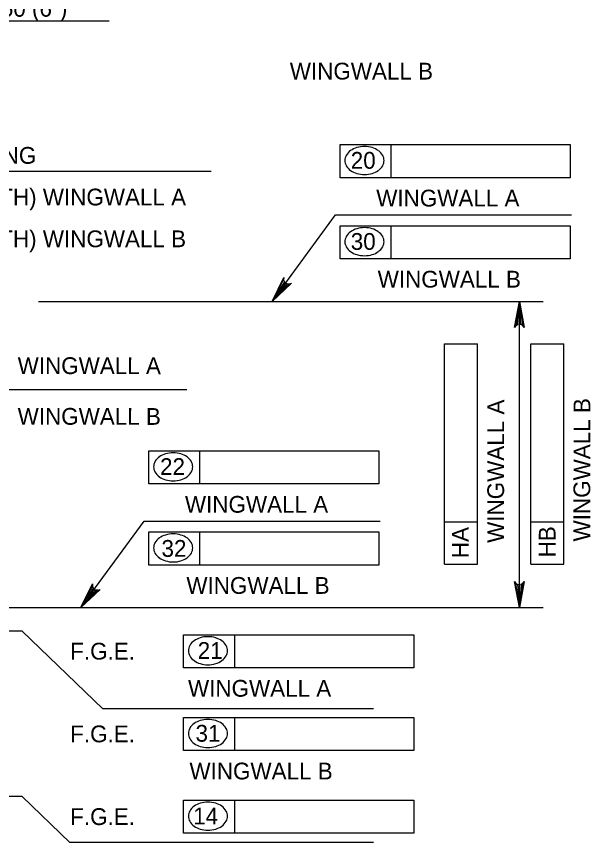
# Model space of a CAD drawing. Extents: x 635440 to 640306, y 296653 to 298484.
# Drawn here: x 638935.8 to 639038.5, y 296781 to 296928.7 of the extents above; entities that cross this region are included whole.
import ezdxf

# ---------------------------------------------------------------- set-up
doc = ezdxf.new("R2010")
doc.units = 0
doc.layers.add('5', color=7, linetype='Continuous')

msp = doc.modelspace()

# ---------------------------------------------------------------- linework, layer by layer
at = {"layer": '5'}
for p, q in [((638930.43, 296927.96), (638952.38, 296927.96)), ((638993.67, 296899.9), (638993.67, 296905.81)), ((638993.67, 296905.81), (639034.88, 296905.81)), ((639002.84, 296899.9), (639002.84, 296905.81)), ((639034.88, 296905.81), (639034.88, 296899.9)), ((638876.92, 296901.05), (638970.61, 296901.05)), ((639034.88, 296899.9), (638993.67, 296899.9)), ((638993.67, 296891.31), (639034.88, 296891.31)), ((638993.67, 296885.4), (638993.67, 296891.31)), ((639002.84, 296885.4), (639002.84, 296891.31)), ((639034.88, 296891.31), (639034.88, 296885.4)), ((639034.88, 296885.4), (638993.67, 296885.4)), ((638939.73, 296877.78), (639030.02, 296877.78)), ((639025.77, 296823.03), (639025.77, 296877.78)), ((639012.37, 296830.81), (639012.37, 296870.18)), ((639012.37, 296870.18), (639018.27, 296870.18)), ((639018.27, 296830.81), (639018.27, 296870.18)), ((639027.79, 296870.18), (639033.7, 296870.18)), ((639027.79, 296830.81), (639027.79, 296870.18)), ((639033.7, 296830.81), (639033.7, 296870.18)), ((638966.27, 296861.99), (638891.42, 296861.99)), ((638959.43, 296851.06), (639000.64, 296851.06)), ((638959.43, 296845.15), (638959.43, 296851.06)), ((638968.6, 296845.15), (638968.6, 296851.06)), ((639000.64, 296851.06), (639000.64, 296845.15)), ((639000.64, 296845.15), (638959.43, 296845.15)), ((639012.37, 296838.37), (639018.27, 296838.37)), ((639027.79, 296838.37), (639033.7, 296838.37)), ((638959.43, 296836.56), (639000.64, 296836.56)), ((638959.43, 296830.65), (638959.43, 296836.56)), ((638968.6, 296830.65), (638968.6, 296836.56)), ((639000.64, 296836.56), (639000.64, 296830.65)), ((639000.64, 296830.65), (638959.43, 296830.65)), ((639012.37, 296830.81), (639018.27, 296830.81)), ((639027.79, 296830.81), (639033.7, 296830.81)), ((638928.57, 296823.03), (639030.02, 296823.03)), ((638936.79, 296818.84), (638928.51, 296818.84)), ((638936.79, 296818.84), (638951.22, 296804.94)), ((638965.65, 296818.18), (639006.86, 296818.18)), ((638965.65, 296812.27), (638965.65, 296818.18)), ((638974.82, 296812.27), (638974.82, 296818.18)), ((639006.86, 296818.18), (639006.86, 296812.27)), ((639006.86, 296812.27), (638965.65, 296812.27)), ((638999.65, 296804.94), (638951.22, 296804.94)), ((638965.65, 296803.38), (639006.86, 296803.38)), ((638965.65, 296797.47), (638965.65, 296803.38)), ((638974.82, 296797.47), (638974.82, 296803.38)), ((639006.86, 296803.38), (639006.86, 296797.47)), ((639006.86, 296797.47), (638965.65, 296797.47)), ((638936.79, 296789.26), (638841.21, 296789.26)), ((638936.79, 296789.26), (638945.31, 296781.05)), ((638965.65, 296788.59), (639006.86, 296788.59)), ((638965.65, 296782.69), (638965.65, 296788.59)), ((638974.82, 296782.69), (638974.82, 296788.59)), ((639006.86, 296788.59), (639006.86, 296782.69)), ((639006.86, 296782.69), (638965.65, 296782.69)), ((638999.65, 296781.05), (638945.31, 296781.05))]:
    msp.add_line(p, q, dxfattribs=at)
for points in [[(638981.54, 296877.78), (638992.88, 296893.27), (639035.07, 296893.27)], [(638981.54, 296877.78), (638983.59, 296882.05), (638983.58, 296881.62), (638983.72, 296881.28), (638983.94, 296881.05), (638984.23, 296880.91), (638984.59, 296880.88), (638985, 296881.02), (638981.54, 296877.78), (638984.59, 296880.88), (638984.23, 296880.91), (638981.54, 296877.78), (638983.94, 296881.05), (638983.72, 296881.28), (638981.54, 296877.78), (638983.58, 296881.62)], [(639025.77, 296877.78), (639026.64, 296873.12), (639026.4, 296873.47), (639026.08, 296873.66), (639025.77, 296873.71), (639025.46, 296873.66), (639025.15, 296873.47), (639024.9, 296873.12), (639025.77, 296877.78), (639025.15, 296873.47), (639025.46, 296873.66), (639025.77, 296877.78), (639025.77, 296873.71), (639026.08, 296873.66), (639025.77, 296877.78), (639026.4, 296873.47)], [(638947.3, 296823.03), (638958.64, 296838.52), (639000.84, 296838.52)], [(639025.77, 296823.03), (639024.9, 296827.69), (639025.15, 296827.33), (639025.46, 296827.14), (639025.77, 296827.09), (639026.08, 296827.14), (639026.4, 296827.33), (639026.64, 296827.69), (639025.77, 296823.03), (639026.4, 296827.33), (639026.08, 296827.14), (639025.77, 296823.03), (639025.77, 296827.09), (639025.46, 296827.14), (639025.77, 296823.03), (639025.15, 296827.33)], [(638947.3, 296823.03), (638949.35, 296827.3), (638949.34, 296826.87), (638949.48, 296826.53), (638949.7, 296826.3), (638949.99, 296826.16), (638950.35, 296826.13), (638950.76, 296826.27), (638947.3, 296823.03), (638950.35, 296826.13), (638949.99, 296826.16), (638947.3, 296823.03), (638949.7, 296826.3), (638949.48, 296826.53), (638947.3, 296823.03), (638949.34, 296826.87)]]:
    msp.add_lwpolyline(points, dxfattribs=at)
for points in [[(638981.54, 296877.78), (638983.49, 296880.01), (638983.09, 296880.31)], [(639025.3, 296874.94), (639026.24, 296874.94), (639025.77, 296877.78)], [(638947.3, 296823.03), (638949.25, 296825.26), (638948.85, 296825.55)], [(639025.3, 296825.86), (639026.24, 296825.86), (639025.77, 296823.03)]]:
    msp.add_lwpolyline(points, close=True, dxfattribs=at)
for centre, radius, start, end in [((638997.17, 296902.5), 2.76, 125.6316, 149.9767), ((638997.7, 296901.76), 3.66, 106.5358, 125.6316), ((638998.05, 296900.6), 4.87, 90, 106.5358), ((638998.05, 296900.6), 4.87, 73.4642, 90), ((638998.39, 296901.76), 3.66, 54.3684, 73.4642), ((638998.92, 296902.5), 2.76, 30.0233, 54.3684), ((638996.37, 296902.96), 1.83, 149.9767, 180), ((638996.37, 296902.96), 1.83, 180, 210.0233), ((638999.72, 296902.96), 1.83, 0, 30.0233), ((638999.72, 296902.96), 1.83, 329.9767, 0), ((638997.17, 296903.43), 2.76, 210.0233, 234.3684), ((638998.92, 296903.43), 2.76, 305.6316, 329.9767), ((638997.7, 296904.16), 3.66, 234.3684, 253.4642), ((638998.05, 296905.32), 4.87, 253.4642, 270), ((638998.05, 296905.32), 4.87, 270, 286.5358), ((638998.39, 296904.16), 3.66, 286.5358, 305.6316), ((638997.17, 296888), 2.76, 125.6316, 149.9767), ((638997.7, 296887.26), 3.66, 106.5358, 125.6316), ((638998.05, 296886.1), 4.87, 90, 106.5358), ((638998.05, 296886.1), 4.87, 73.4642, 90), ((638998.39, 296887.26), 3.66, 54.3684, 73.4642), ((638998.92, 296888), 2.76, 30.0233, 54.3684), ((638996.37, 296888.46), 1.83, 149.9767, 180), ((638996.37, 296888.46), 1.83, 180, 210.0233), ((638999.72, 296888.46), 1.83, 0, 30.0233), ((638999.72, 296888.46), 1.83, 329.9767, 0), ((638997.17, 296888.93), 2.76, 210.0233, 234.3684), ((638997.7, 296889.66), 3.66, 234.3684, 253.4642), ((638998.39, 296889.66), 3.66, 286.5358, 305.6316), ((638998.92, 296888.93), 2.76, 305.6316, 329.9767), ((638998.05, 296890.82), 4.87, 253.4642, 270), ((638998.05, 296890.82), 4.87, 270, 286.5358), ((638962.94, 296847.75), 2.76, 125.6316, 149.9767), ((638963.46, 296847.01), 3.66, 106.5358, 125.6316), ((638963.81, 296845.85), 4.87, 90, 106.5358), ((638963.81, 296845.85), 4.87, 73.4642, 90), ((638964.15, 296847.01), 3.66, 54.3684, 73.4642), ((638964.68, 296847.75), 2.76, 30.0233, 54.3684), ((638962.13, 296848.21), 1.83, 149.9767, 180), ((638965.48, 296848.21), 1.83, 0, 30.0233), ((638962.13, 296848.21), 1.83, 180, 210.0233), ((638962.94, 296848.68), 2.76, 210.0233, 234.3684), ((638964.68, 296848.68), 2.76, 305.6316, 329.9767), ((638965.48, 296848.21), 1.83, 329.9767, 0), ((638963.46, 296849.41), 3.66, 234.3684, 253.4642), ((638963.81, 296850.57), 4.87, 253.4642, 270), ((638963.81, 296850.57), 4.87, 270, 286.5358), ((638964.15, 296849.41), 3.66, 286.5358, 305.6316), ((638962.94, 296833.25), 2.76, 125.6316, 149.9767), ((638963.46, 296832.51), 3.66, 106.5358, 125.6316), ((638963.81, 296831.35), 4.87, 90, 106.5358), ((638963.81, 296831.35), 4.87, 73.4642, 90), ((638964.15, 296832.51), 3.66, 54.3684, 73.4642), ((638964.68, 296833.25), 2.76, 30.0233, 54.3684), ((638962.13, 296833.71), 1.83, 149.9767, 180), ((638962.13, 296833.71), 1.83, 180, 210.0233), ((638965.48, 296833.71), 1.83, 0, 30.0233), ((638965.48, 296833.71), 1.83, 329.9767, 0), ((638962.94, 296834.18), 2.76, 210.0233, 234.3684), ((638964.68, 296834.18), 2.76, 305.6316, 329.9767), ((638963.46, 296834.91), 3.66, 234.3684, 253.4642), ((638963.81, 296836.07), 4.87, 253.4642, 270), ((638963.81, 296836.07), 4.87, 270, 286.5358), ((638964.15, 296834.91), 3.66, 286.5358, 305.6316), ((638969.68, 296814.13), 3.66, 106.5358, 125.6316), ((638970.02, 296812.97), 4.87, 90, 106.5358), ((638970.02, 296812.97), 4.87, 73.4642, 90), ((638970.37, 296814.13), 3.66, 54.3684, 73.4642), ((638968.35, 296815.33), 1.83, 149.9767, 180), ((638969.15, 296814.87), 2.76, 125.6316, 149.9767), ((638970.9, 296814.87), 2.76, 30.0233, 54.3684), ((638971.7, 296815.33), 1.83, 0, 30.0233), ((638968.35, 296815.33), 1.83, 180, 210.0233), ((638969.15, 296815.8), 2.76, 210.0233, 234.3684), ((638970.9, 296815.8), 2.76, 305.6316, 329.9767), ((638971.7, 296815.33), 1.83, 329.9767, 0), ((638969.68, 296816.53), 3.66, 234.3684, 253.4642), ((638970.02, 296817.69), 4.87, 253.4642, 270), ((638970.02, 296817.69), 4.87, 270, 286.5358), ((638970.37, 296816.53), 3.66, 286.5358, 305.6316), ((638969.68, 296799.33), 3.66, 106.5358, 125.6316), ((638970.02, 296798.17), 4.87, 90, 106.5358), ((638970.02, 296798.17), 4.87, 73.4642, 90), ((638970.37, 296799.33), 3.66, 54.3684, 73.4642), ((638968.35, 296800.53), 1.83, 149.9767, 180), ((638969.15, 296800.07), 2.76, 125.6316, 149.9767), ((638970.9, 296800.07), 2.76, 30.0233, 54.3684), ((638971.7, 296800.53), 1.83, 0, 30.0233), ((638968.35, 296800.53), 1.83, 180, 210.0233), ((638969.15, 296801), 2.76, 210.0233, 234.3684), ((638970.9, 296801), 2.76, 305.6316, 329.9767), ((638971.7, 296800.53), 1.83, 329.9767, 0), ((638969.68, 296801.73), 3.66, 234.3684, 253.4642), ((638970.02, 296802.89), 4.87, 253.4642, 270), ((638970.02, 296802.89), 4.87, 270, 286.5358), ((638970.37, 296801.73), 3.66, 286.5358, 305.6316), ((638969.68, 296784.55), 3.66, 106.5358, 125.6316), ((638970.02, 296783.39), 4.87, 90, 106.5358), ((638970.02, 296783.39), 4.87, 73.4642, 90), ((638970.37, 296784.55), 3.66, 54.3684, 73.4642), ((638968.35, 296785.75), 1.83, 149.9767, 180), ((638969.15, 296785.28), 2.76, 125.6316, 149.9767), ((638970.9, 296785.28), 2.76, 30.0233, 54.3684), ((638971.7, 296785.75), 1.83, 0, 30.0233), ((638968.35, 296785.75), 1.83, 180, 210.0233), ((638969.15, 296786.22), 2.76, 210.0233, 234.3684), ((638970.9, 296786.22), 2.76, 305.6316, 329.9767), ((638971.7, 296785.75), 1.83, 329.9767, 0), ((638969.68, 296786.95), 3.66, 234.3684, 253.4642), ((638970.02, 296788.11), 4.87, 253.4642, 270), ((638970.02, 296788.11), 4.87, 270, 286.5358), ((638970.37, 296786.95), 3.66, 286.5358, 305.6316)]:
    msp.add_arc(centre, radius, start, end, dxfattribs=at)

# ---------------------------------------------------------------- texts
for s, height, p in [('150 (6")', 3, (638930.73, 296928.68)), ('WINGWALL B', 3, (638984.68, 296917.45)), ('130x450 (6"x18") WING COPING', 3.0001, (638879.61, 296902.39)), ('20', 3, (638995.59, 296901.5)), ('(LENGTH) WINGWALL A', 3.0001, (638920.42, 296894.94)), ('WINGWALL A', 3, (639000.15, 296894.75)), ('(LENGTH) WINGWALL B', 3.0001, (638920.42, 296887.47)), ('30', 3, (638995.59, 296887)), ('WINGWALL B', 3, (639000.41, 296880.25)), ('22', 3, (638961.46, 296846.75)), ('WINGWALL A', 3, (638965.91, 296840)), ('32', 3, (638961.72, 296832.12)), ('WINGWALL B', 3, (638966.17, 296825.5)), ('F.G.E.', 3, (638945.38, 296813.75)), ('21', 3, (638968.2, 296813.87)), ('WINGWALL A', 3, (638966.46, 296807.11)), ('F.G.E.', 3, (638945.38, 296798.96)), ('31', 3, (638967.81, 296799.07)), ('WINGWALL B', 3, (638966.72, 296792.32)), ('F.G.E.', 3, (638945.38, 296784.17)), ('14', 3, (638967.39, 296784.29))]:
    msp.add_text(s, height=height, dxfattribs=at).set_placement(p)
for s, rotation, p in [('WINGWALL A', 359.9382, (638935.97, 296864.8)), ('WINGWALL A', 89.9382, (639023.02, 296834.6)), ('WINGWALL B', 89.9382, (639038.44, 296834.86)), ('WINGWALL B', 359.9382, (638935.97, 296855.74)), ('HA', 89.9382, (639016.69, 296831.88)), ('HB', 89.9382, (639032.24, 296832.01))]:
    msp.add_text(s, height=3, rotation=rotation, dxfattribs=at).set_placement(p)

doc.saveas('drawing.dxf')
